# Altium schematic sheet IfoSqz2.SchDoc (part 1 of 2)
size C; Engineer: Daniel Sigg; DocumentNumber: 5; SheetNumber: 17; SheetTotal: 33
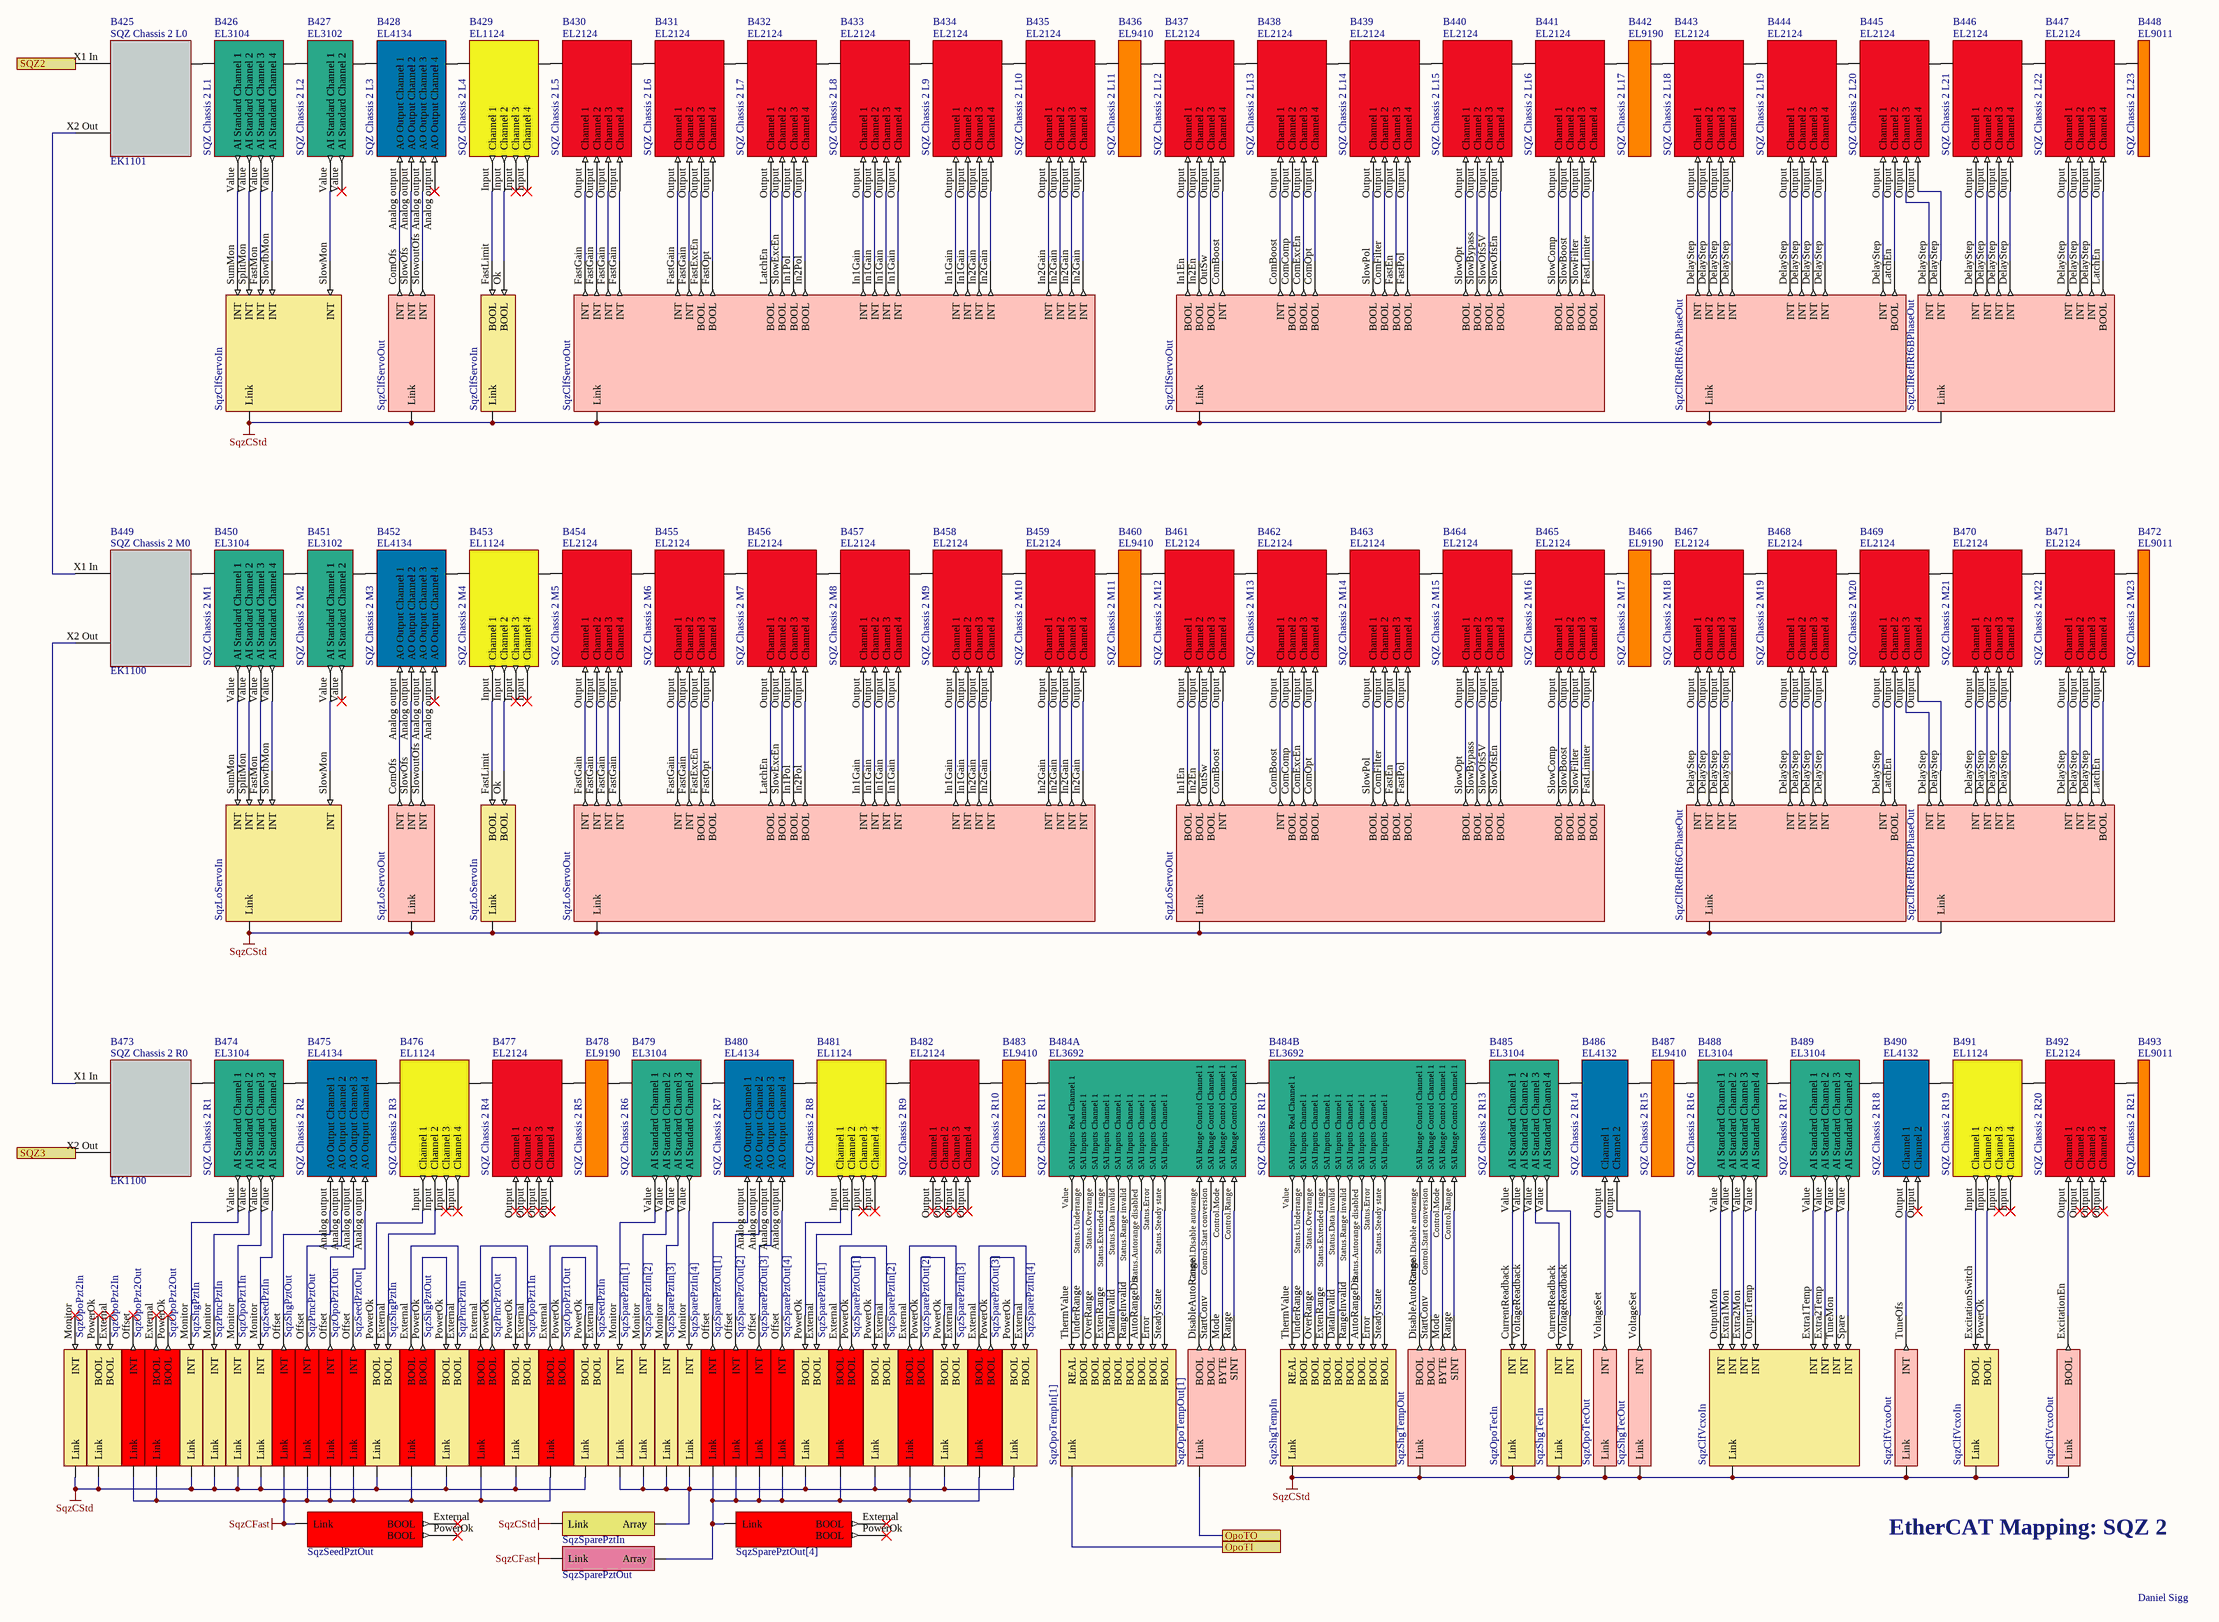
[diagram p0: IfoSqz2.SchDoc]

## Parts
B425  SQZ Chassis 2 L0  Part Number: EK1101
B426  SQZ Chassis 2 L1  Part Number: EL3104  (mechanical)
B427  SQZ Chassis 2 L2  Part Number: EL3102  (mechanical)
B428  SQZ Chassis 2 L3  Part Number: EL4134  (mechanical)
B429  SQZ Chassis 2 L4  Part Number: EL1124  (mechanical)
B430  SQZ Chassis 2 L5  Part Number: EL2124  (mechanical)
B431  SQZ Chassis 2 L6  Part Number: EL2124  (mechanical)
B432  SQZ Chassis 2 L7  Part Number: EL2124  (mechanical)
B433  SQZ Chassis 2 L8  Part Number: EL2124  (mechanical)
B434  SQZ Chassis 2 L9  Part Number: EL2124  (mechanical)
B435  SQZ Chassis 2 L10  Part Number: EL2124  (mechanical)
B436  SQZ Chassis 2 L11  Part Number: EL9410  (mechanical)
B437  SQZ Chassis 2 L12  Part Number: EL2124  (mechanical)
B438  SQZ Chassis 2 L13  Part Number: EL2124  (mechanical)
B439  SQZ Chassis 2 L14  Part Number: EL2124  (mechanical)
B440  SQZ Chassis 2 L15  Part Number: EL2124  (mechanical)
B441  SQZ Chassis 2 L16  Part Number: EL2124  (mechanical)
B442  SQZ Chassis 2 L17  Part Number: EL9190  (mechanical)
B443  SQZ Chassis 2 L18  Part Number: EL2124  (mechanical)
B444  SQZ Chassis 2 L19  Part Number: EL2124  (mechanical)
B445  SQZ Chassis 2 L20  Part Number: EL2124  (mechanical)
B446  SQZ Chassis 2 L21  Part Number: EL2124  (mechanical)
B447  SQZ Chassis 2 L22  Part Number: EL2124  (mechanical)
B448  SQZ Chassis 2 L23  Part Number: EL9011  (mechanical)
B449  SQZ Chassis 2 M0  Part Number: EK1100
B450  SQZ Chassis 2 M1  Part Number: EL3104  (mechanical)
B451  SQZ Chassis 2 M2  Part Number: EL3102  (mechanical)
B452  SQZ Chassis 2 M3  Part Number: EL4134  (mechanical)
B453  SQZ Chassis 2 M4  Part Number: EL1124  (mechanical)
B454  SQZ Chassis 2 M5  Part Number: EL2124  (mechanical)
B455  SQZ Chassis 2 M6  Part Number: EL2124  (mechanical)
B456  SQZ Chassis 2 M7  Part Number: EL2124  (mechanical)
B457  SQZ Chassis 2 M8  Part Number: EL2124  (mechanical)
B458  SQZ Chassis 2 M9  Part Number: EL2124  (mechanical)
B459  SQZ Chassis 2 M10  Part Number: EL2124  (mechanical)
B460  SQZ Chassis 2 M11  Part Number: EL9410  (mechanical)
B461  SQZ Chassis 2 M12  Part Number: EL2124  (mechanical)
B462  SQZ Chassis 2 M13  Part Number: EL2124  (mechanical)
B463  SQZ Chassis 2 M14  Part Number: EL2124  (mechanical)
B464  SQZ Chassis 2 M15  Part Number: EL2124  (mechanical)
B465  SQZ Chassis 2 M16  Part Number: EL2124  (mechanical)
B466  SQZ Chassis 2 M17  Part Number: EL9190  (mechanical)
B467  SQZ Chassis 2 M18  Part Number: EL2124  (mechanical)
B468  SQZ Chassis 2 M19  Part Number: EL2124  (mechanical)
B469  SQZ Chassis 2 M20  Part Number: EL2124  (mechanical)
B470  SQZ Chassis 2 M21  Part Number: EL2124  (mechanical)
B471  SQZ Chassis 2 M22  Part Number: EL2124  (mechanical)
B472  SQZ Chassis 2 M23  Part Number: EL9011  (mechanical)
B473  SQZ Chassis 2 R0  Part Number: EK1100
B474  SQZ Chassis 2 R1  Part Number: EL3104  (mechanical)
B475  SQZ Chassis 2 R2  Part Number: EL4134  (mechanical)
B476  SQZ Chassis 2 R3  Part Number: EL1124  (mechanical)
B477  SQZ Chassis 2 R4  Part Number: EL2124  (mechanical)
B478  SQZ Chassis 2 R5  Part Number: EL9190  (mechanical)
B479  SQZ Chassis 2 R6  Part Number: EL3104  (mechanical)
B480  SQZ Chassis 2 R7  Part Number: EL4134  (mechanical)
B481  SQZ Chassis 2 R8  Part Number: EL1124  (mechanical)
B482  SQZ Chassis 2 R9  Part Number: EL2124  (mechanical)
B483  SQZ Chassis 2 R10  Part Number: EL9410  (mechanical)
B484A  SQZ Chassis 2 R11  Part Number: EL3692  (mechanical)
B484B  SQZ Chassis 2 R12  Part Number: EL3692  (mechanical)
B485  SQZ Chassis 2 R13  Part Number: EL3104  (mechanical)
B486  SQZ Chassis 2 R14  Part Number: EL4132  (mechanical)
B487  SQZ Chassis 2 R15  Part Number: EL9410  (mechanical)
B488  SQZ Chassis 2 R16  Part Number: EL3104  (mechanical)
B489  SQZ Chassis 2 R17  Part Number: EL3104  (mechanical)
B490  SQZ Chassis 2 R18  Part Number: EL4132  (mechanical)
B491  SQZ Chassis 2 R19  Part Number: EL1124  (mechanical)
B492  SQZ Chassis 2 R20  Part Number: EL2124  (mechanical)
B493  SQZ Chassis 2 R21  Part Number: EL9011  (mechanical)
V176  SqzShgTecIn  (no BOM)
V177  SqzShgTecOut  (no BOM)
V289  SqzLoServoIn  (parts A,B of 2)  (no BOM)
V290  SqzLoServoOut  (parts A,B,C of 3)  (no BOM)
V291  SqzClfServoIn  (parts A,B of 2)  (no BOM)
V292  SqzClfServoOut  (parts A,B,C of 3)  (no BOM)
V297  SqzShgTempIn  (no BOM)
V298  SqzShgTempOut  (no BOM)
V303  SqzClfVcxoIn  (parts A,B of 2)  (no BOM)
V304  SqzClfVcxoOut  (parts A,B of 2)  (no BOM)
V305  SqzShgPztIn  (parts A,B of 2)  (no BOM)
V306  SqzPmcPztIn  (parts A,B of 2)  (no BOM)
V307  SqzOpoPzt1In  (parts A,B of 2)  (no BOM)
V308  SqzSeedPztIn  (parts A,B of 2)  (no BOM)
V309  SqzShgPztOut  (parts A,B of 2)  (no BOM)
V310  SqzPmcPztOut  (parts A,B of 2)  (no BOM)
V311  SqzOpoPzt1Out  (parts A,B of 2)  (no BOM)
V312  SqzSeedPztOut  (parts A,B of 2)  (no BOM)
V313  SqzSparePztIn[1]  (parts A,B of 2)  (no BOM)
V314  SqzSparePztIn[2]  (parts A,B of 2)  (no BOM)
V315  SqzSparePztIn[3]  (parts A,B of 2)  (no BOM)
V316  SqzSparePztIn[4]  (parts A,B of 2)  (no BOM)
V317  SqzSparePztOut[1]  (parts A,B of 2)  (no BOM)
V318  SqzSparePztOut[2]  (parts A,B of 2)  (no BOM)
V319  SqzSparePztOut[3]  (parts A,B of 2)  (no BOM)
V320  SqzSparePztOut[4]  (parts A,B of 2)  (no BOM)
V448  SqzClfReflRf6APhaseOut  (no BOM)
V449  SqzClfReflRf6BPhaseOut  (no BOM)
V450  SqzClfReflRf6CPhaseOut  (no BOM)
V452  SqzClfReflRf6DPhaseOut  (no BOM)
V453  SqzOpoTempIn[1]  (no BOM)
V454  SqzOpoTempOut[1]  (no BOM)
V455  SqzOpoTecIn  (no BOM)
V456  SqzOpoTecOut  (no BOM)
V457  SqzSparePztIn  (no BOM)
V458  SqzSparePztOut  (no BOM)
V655  SqzOpoPzt2In  (parts A,B of 2)  (no BOM)
V668  SqzOpoPzt2Out  (parts A,B of 2)  (no BOM)

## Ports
OpoTI, OpoTO, SQZ2, SQZ3

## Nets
SqzCFast: V309.0(Link) V309.1(Link) V310.0(Link) V310.1(Link) V311.0(Link) V311.1(Link) V312.0(Link) V312.1(Link) V458.?1(Link) V668.0(Link) V668.1(Link)
SqzCStd: V176.1(Link) V177.1(Link) V289.0(Link) V289.1(Link) V290.0(Link) V290.1(Link) V290.2(Link) V291.0(Link) V291.1(Link) V292.0(Link) V292.1(Link) V292.2(Link) V297.1(Link) V298.1(Link) V303.0(Link) V303.1(Link) V304.0(Link) V304.1(Link) V305.0(Link) V305.1(Link) V306.0(Link) V306.1(Link) V307.0(Link) V307.1(Link) V308.0(Link) V308.1(Link) V448.?1(Link) V449.?1(Link) V450.?1(Link) V452.?1(Link) V455.1(Link) V456.1(Link) V457.?1(Link) V655.0(Link) V655.1(Link)
OpoTI: V453.1(Link) ; port OpoTI
OpoTO: V454.1(Link) ; port OpoTO
SQZ2: B425.X1_In(A) ; port SQZ2
SQZ3: B473.X2_Out(C) ; port SQZ3
NetB425_Ebus: B425.Ebus(B) B426.Ebus(A)
NetB425_X2 Out: B425.X2_Out(C) B449.X1_In(A)
NetB426_Ebus: B426.Ebus(B) B427.Ebus(A)
NetB426_Value: B426.Value(AI_Standard_Channel_1) V291.SumMon(INT)
NetB426_Value: B426.Value(AI_Standard_Channel_2) V291.SplitMon(INT)  [a separate net that carries the same name]
NetB426_Value: B426.Value(AI_Standard_Channel_3) V291.FastMon(INT)  [a separate net that carries the same name]
NetB426_Value: B426.Value(AI_Standard_Channel_4) V291.SlowfbMon(INT)  [a separate net that carries the same name]
NetB427_Ebus: B427.Ebus(B) B428.Ebus(A)
NetB427_Value: B427.Value(AI_Standard_Channel_1) V291.SlowMon(INT)
NetB428_Analog output: B428.Analog_output(AO_Output_Channel_1) V292.ComOfs(INT)
NetB428_Analog output: B428.Analog_output(AO_Output_Channel_2) V292.SlowOfs(INT)  [a separate net that carries the same name]
NetB428_Analog output: B428.Analog_output(AO_Output_Channel_3) V292.SlowoutOfs(INT)  [a separate net that carries the same name]
NetB428_Ebus: B428.Ebus(B) B429.Ebus(A)
NetB429_Ebus: B429.Ebus(B) B430.Ebus(A)
NetB429_Input: B429.Input(Channel_1) V291.FastLimit(BOOL)
NetB429_Input: B429.Input(Channel_2) V291.Ok(BOOL)  [a separate net that carries the same name]
NetB430_Ebus: B430.Ebus(B) B431.Ebus(A)
NetB430_Output: B430.Output(Channel_1) V292.FastGain(INT)
NetB430_Output: B430.Output(Channel_2) V292.FastGain(INT)  [a separate net that carries the same name]
NetB430_Output: B430.Output(Channel_3) V292.FastGain(INT)  [a separate net that carries the same name]
NetB430_Output: B430.Output(Channel_4) V292.FastGain(INT)  [a separate net that carries the same name]
NetB431_Ebus: B431.Ebus(B) B432.Ebus(A)
NetB431_Output: B431.Output(Channel_1) V292.FastGain(INT)
NetB431_Output: B431.Output(Channel_2) V292.FastGain(INT)  [a separate net that carries the same name]
NetB431_Output: B431.Output(Channel_3) V292.FastExcEn(BOOL)  [a separate net that carries the same name]
NetB431_Output: B431.Output(Channel_4) V292.FastOpt(BOOL)  [a separate net that carries the same name]
NetB432_Ebus: B432.Ebus(B) B433.Ebus(A)
NetB432_Output: B432.Output(Channel_1) V292.LatchEn(BOOL)
NetB432_Output: B432.Output(Channel_2) V292.SlowExcEn(BOOL)  [a separate net that carries the same name]
NetB432_Output: B432.Output(Channel_3) V292.In1Pol(BOOL)  [a separate net that carries the same name]
NetB432_Output: B432.Output(Channel_4) V292.In2Pol(BOOL)  [a separate net that carries the same name]
NetB433_Ebus: B433.Ebus(B) B434.Ebus(A)
NetB433_Output: B433.Output(Channel_1) V292.In1Gain(INT)
NetB433_Output: B433.Output(Channel_2) V292.In1Gain(INT)  [a separate net that carries the same name]
NetB433_Output: B433.Output(Channel_3) V292.In1Gain(INT)  [a separate net that carries the same name]
NetB433_Output: B433.Output(Channel_4) V292.In1Gain(INT)  [a separate net that carries the same name]
NetB434_Ebus: B434.Ebus(B) B435.Ebus(A)
NetB434_Output: B434.Output(Channel_1) V292.In1Gain(INT)
NetB434_Output: B434.Output(Channel_2) V292.In1Gain(INT)  [a separate net that carries the same name]
NetB434_Output: B434.Output(Channel_3) V292.In2Gain(INT)  [a separate net that carries the same name]
NetB434_Output: B434.Output(Channel_4) V292.In2Gain(INT)  [a separate net that carries the same name]
NetB435_Ebus: B435.Ebus(B) B436.Ebus(A)
NetB435_Output: B435.Output(Channel_1) V292.In2Gain(INT)
NetB435_Output: B435.Output(Channel_2) V292.In2Gain(INT)  [a separate net that carries the same name]
NetB435_Output: B435.Output(Channel_3) V292.In2Gain(INT)  [a separate net that carries the same name]
NetB435_Output: B435.Output(Channel_4) V292.In2Gain(INT)  [a separate net that carries the same name]
NetB436_Ebus: B436.Ebus(B) B437.Ebus(A)
NetB437_Ebus: B437.Ebus(B) B438.Ebus(A)
NetB437_Output: B437.Output(Channel_1) V292.In1En(BOOL)
NetB437_Output: B437.Output(Channel_2) V292.In2En(BOOL)  [a separate net that carries the same name]
NetB437_Output: B437.Output(Channel_3) V292.OutSw(BOOL)  [a separate net that carries the same name]
NetB437_Output: B437.Output(Channel_4) V292.ComBoost(INT)  [a separate net that carries the same name]
NetB438_Ebus: B438.Ebus(B) B439.Ebus(A)
NetB438_Output: B438.Output(Channel_1) V292.ComBoost(INT)
NetB438_Output: B438.Output(Channel_2) V292.ComComp(BOOL)  [a separate net that carries the same name]
NetB438_Output: B438.Output(Channel_3) V292.ComExcEn(BOOL)  [a separate net that carries the same name]
NetB438_Output: B438.Output(Channel_4) V292.ComOpt(BOOL)  [a separate net that carries the same name]
NetB439_Ebus: B439.Ebus(B) B440.Ebus(A)
NetB439_Output: B439.Output(Channel_1) V292.SlowPol(BOOL)
NetB439_Output: B439.Output(Channel_2) V292.ComFilter(BOOL)  [a separate net that carries the same name]
NetB439_Output: B439.Output(Channel_3) V292.FastEn(BOOL)  [a separate net that carries the same name]
NetB439_Output: B439.Output(Channel_4) V292.FastPol(BOOL)  [a separate net that carries the same name]
NetB440_Ebus: B440.Ebus(B) B441.Ebus(A)
NetB440_Output: B440.Output(Channel_1) V292.SlowOpt(BOOL)
NetB440_Output: B440.Output(Channel_2) V292.SlowBypass(BOOL)  [a separate net that carries the same name]
NetB440_Output: B440.Output(Channel_3) V292.SlowOfs5V(BOOL)  [a separate net that carries the same name]
NetB440_Output: B440.Output(Channel_4) V292.SlowOfsEn(BOOL)  [a separate net that carries the same name]
NetB441_Ebus: B441.Ebus(B) B442.Ebus(A)
NetB441_Output: B441.Output(Channel_1) V292.SlowComp(BOOL)
NetB441_Output: B441.Output(Channel_2) V292.SlowBoost(BOOL)  [a separate net that carries the same name]
NetB441_Output: B441.Output(Channel_3) V292.SlowFilter(BOOL)  [a separate net that carries the same name]
NetB441_Output: B441.Output(Channel_4) V292.FastLimiter(BOOL)  [a separate net that carries the same name]
NetB442_Ebus: B442.Ebus(B) B443.Ebus(A)
NetB443_Ebus: B443.Ebus(B) B444.Ebus(A)
NetB443_Output: B443.Output(Channel_1) V448.DelayStep(INT)
NetB443_Output: B443.Output(Channel_2) V448.DelayStep(INT)  [a separate net that carries the same name]
NetB443_Output: B443.Output(Channel_3) V448.DelayStep(INT)  [a separate net that carries the same name]
NetB443_Output: B443.Output(Channel_4) V448.DelayStep(INT)  [a separate net that carries the same name]
NetB444_Ebus: B444.Ebus(B) B445.Ebus(A)
NetB444_Output: B444.Output(Channel_1) V448.DelayStep(INT)
NetB444_Output: B444.Output(Channel_2) V448.DelayStep(INT)  [a separate net that carries the same name]
NetB444_Output: B444.Output(Channel_3) V448.DelayStep(INT)  [a separate net that carries the same name]
NetB444_Output: B444.Output(Channel_4) V448.DelayStep(INT)  [a separate net that carries the same name]
NetB445_Ebus: B445.Ebus(B) B446.Ebus(A)
NetB445_Output: B445.Output(Channel_1) V448.DelayStep(INT)
NetB445_Output: B445.Output(Channel_2) V448.LatchEn(BOOL)  [a separate net that carries the same name]
NetB445_Output: B445.Output(Channel_3) V449.DelayStep(INT)  [a separate net that carries the same name]
NetB445_Output: B445.Output(Channel_4) V449.DelayStep(INT)  [a separate net that carries the same name]
NetB446_Ebus: B446.Ebus(B) B447.Ebus(A)
NetB446_Output: B446.Output(Channel_1) V449.DelayStep(INT)
NetB446_Output: B446.Output(Channel_2) V449.DelayStep(INT)  [a separate net that carries the same name]
NetB446_Output: B446.Output(Channel_3) V449.DelayStep(INT)  [a separate net that carries the same name]
NetB446_Output: B446.Output(Channel_4) V449.DelayStep(INT)  [a separate net that carries the same name]
NetB447_Ebus: B447.Ebus(B) B448.Ebus(A)
NetB447_Output: B447.Output(Channel_1) V449.DelayStep(INT)
NetB447_Output: B447.Output(Channel_2) V449.DelayStep(INT)  [a separate net that carries the same name]
NetB447_Output: B447.Output(Channel_3) V449.DelayStep(INT)  [a separate net that carries the same name]
NetB447_Output: B447.Output(Channel_4) V449.LatchEn(BOOL)  [a separate net that carries the same name]
NetB449_Ebus: B449.Ebus(B) B450.Ebus(A)
NetB449_X2 Out: B449.X2_Out(C) B473.X1_In(A)
NetB450_Ebus: B450.Ebus(B) B451.Ebus(A)
NetB450_Value: B450.Value(AI_Standard_Channel_1) V289.SumMon(INT)
NetB450_Value: B450.Value(AI_Standard_Channel_2) V289.SplitMon(INT)  [a separate net that carries the same name]
NetB450_Value: B450.Value(AI_Standard_Channel_3) V289.FastMon(INT)  [a separate net that carries the same name]
NetB450_Value: B450.Value(AI_Standard_Channel_4) V289.SlowfbMon(INT)  [a separate net that carries the same name]
NetB451_Ebus: B451.Ebus(B) B452.Ebus(A)
NetB451_Value: B451.Value(AI_Standard_Channel_1) V289.SlowMon(INT)
NetB452_Analog output: B452.Analog_output(AO_Output_Channel_1) V290.ComOfs(INT)
NetB452_Analog output: B452.Analog_output(AO_Output_Channel_2) V290.SlowOfs(INT)  [a separate net that carries the same name]
NetB452_Analog output: B452.Analog_output(AO_Output_Channel_3) V290.SlowoutOfs(INT)  [a separate net that carries the same name]
NetB452_Ebus: B452.Ebus(B) B453.Ebus(A)
NetB453_Ebus: B453.Ebus(B) B454.Ebus(A)
NetB453_Input: B453.Input(Channel_1) V289.FastLimit(BOOL)
NetB453_Input: B453.Input(Channel_2) V289.Ok(BOOL)  [a separate net that carries the same name]
NetB454_Ebus: B454.Ebus(B) B455.Ebus(A)
NetB454_Output: B454.Output(Channel_1) V290.FastGain(INT)
NetB454_Output: B454.Output(Channel_2) V290.FastGain(INT)  [a separate net that carries the same name]
NetB454_Output: B454.Output(Channel_3) V290.FastGain(INT)  [a separate net that carries the same name]
NetB454_Output: B454.Output(Channel_4) V290.FastGain(INT)  [a separate net that carries the same name]
NetB455_Ebus: B455.Ebus(B) B456.Ebus(A)
NetB455_Output: B455.Output(Channel_1) V290.FastGain(INT)
NetB455_Output: B455.Output(Channel_2) V290.FastGain(INT)  [a separate net that carries the same name]
NetB455_Output: B455.Output(Channel_3) V290.FastExcEn(BOOL)  [a separate net that carries the same name]
NetB455_Output: B455.Output(Channel_4) V290.FastOpt(BOOL)  [a separate net that carries the same name]
NetB456_Ebus: B456.Ebus(B) B457.Ebus(A)
NetB456_Output: B456.Output(Channel_1) V290.LatchEn(BOOL)
NetB456_Output: B456.Output(Channel_2) V290.SlowExcEn(BOOL)  [a separate net that carries the same name]
NetB456_Output: B456.Output(Channel_3) V290.In1Pol(BOOL)  [a separate net that carries the same name]
NetB456_Output: B456.Output(Channel_4) V290.In2Pol(BOOL)  [a separate net that carries the same name]
NetB457_Ebus: B457.Ebus(B) B458.Ebus(A)
NetB457_Output: B457.Output(Channel_1) V290.In1Gain(INT)
NetB457_Output: B457.Output(Channel_2) V290.In1Gain(INT)  [a separate net that carries the same name]
NetB457_Output: B457.Output(Channel_3) V290.In1Gain(INT)  [a separate net that carries the same name]
NetB457_Output: B457.Output(Channel_4) V290.In1Gain(INT)  [a separate net that carries the same name]
NetB458_Ebus: B458.Ebus(B) B459.Ebus(A)
NetB458_Output: B458.Output(Channel_1) V290.In1Gain(INT)
NetB458_Output: B458.Output(Channel_2) V290.In1Gain(INT)  [a separate net that carries the same name]
NetB458_Output: B458.Output(Channel_3) V290.In2Gain(INT)  [a separate net that carries the same name]
NetB458_Output: B458.Output(Channel_4) V290.In2Gain(INT)  [a separate net that carries the same name]
NetB459_Ebus: B459.Ebus(B) B460.Ebus(A)
NetB459_Output: B459.Output(Channel_1) V290.In2Gain(INT)
NetB459_Output: B459.Output(Channel_2) V290.In2Gain(INT)  [a separate net that carries the same name]
NetB459_Output: B459.Output(Channel_3) V290.In2Gain(INT)  [a separate net that carries the same name]
NetB459_Output: B459.Output(Channel_4) V290.In2Gain(INT)  [a separate net that carries the same name]
NetB460_Ebus: B460.Ebus(B) B461.Ebus(A)
NetB461_Ebus: B461.Ebus(B) B462.Ebus(A)
NetB461_Output: B461.Output(Channel_1) V290.In1En(BOOL)
NetB461_Output: B461.Output(Channel_2) V290.In2En(BOOL)  [a separate net that carries the same name]
NetB461_Output: B461.Output(Channel_3) V290.OutSw(BOOL)  [a separate net that carries the same name]
NetB461_Output: B461.Output(Channel_4) V290.ComBoost(INT)  [a separate net that carries the same name]
NetB462_Ebus: B462.Ebus(B) B463.Ebus(A)
NetB462_Output: B462.Output(Channel_1) V290.ComBoost(INT)
NetB462_Output: B462.Output(Channel_2) V290.ComComp(BOOL)  [a separate net that carries the same name]
NetB462_Output: B462.Output(Channel_3) V290.ComExcEn(BOOL)  [a separate net that carries the same name]
NetB462_Output: B462.Output(Channel_4) V290.ComOpt(BOOL)  [a separate net that carries the same name]
NetB463_Ebus: B463.Ebus(B) B464.Ebus(A)
NetB463_Output: B463.Output(Channel_1) V290.SlowPol(BOOL)
NetB463_Output: B463.Output(Channel_2) V290.ComFilter(BOOL)  [a separate net that carries the same name]
NetB463_Output: B463.Output(Channel_3) V290.FastEn(BOOL)  [a separate net that carries the same name]
NetB463_Output: B463.Output(Channel_4) V290.FastPol(BOOL)  [a separate net that carries the same name]
NetB464_Ebus: B464.Ebus(B) B465.Ebus(A)
NetB464_Output: B464.Output(Channel_1) V290.SlowOpt(BOOL)
NetB464_Output: B464.Output(Channel_2) V290.SlowBypass(BOOL)  [a separate net that carries the same name]
NetB464_Output: B464.Output(Channel_3) V290.SlowOfs5V(BOOL)  [a separate net that carries the same name]
NetB464_Output: B464.Output(Channel_4) V290.SlowOfsEn(BOOL)  [a separate net that carries the same name]
NetB465_Ebus: B465.Ebus(B) B466.Ebus(A)
NetB465_Output: B465.Output(Channel_1) V290.SlowComp(BOOL)
NetB465_Output: B465.Output(Channel_2) V290.SlowBoost(BOOL)  [a separate net that carries the same name]
NetB465_Output: B465.Output(Channel_3) V290.SlowFilter(BOOL)  [a separate net that carries the same name]
NetB465_Output: B465.Output(Channel_4) V290.FastLimiter(BOOL)  [a separate net that carries the same name]
NetB466_Ebus: B466.Ebus(B) B467.Ebus(A)
NetB467_Ebus: B467.Ebus(B) B468.Ebus(A)
NetB467_Output: B467.Output(Channel_1) V450.DelayStep(INT)
NetB467_Output: B467.Output(Channel_2) V450.DelayStep(INT)  [a separate net that carries the same name]
NetB467_Output: B467.Output(Channel_3) V450.DelayStep(INT)  [a separate net that carries the same name]
NetB467_Output: B467.Output(Channel_4) V450.DelayStep(INT)  [a separate net that carries the same name]
NetB468_Ebus: B468.Ebus(B) B469.Ebus(A)
NetB468_Output: B468.Output(Channel_1) V450.DelayStep(INT)
NetB468_Output: B468.Output(Channel_2) V450.DelayStep(INT)  [a separate net that carries the same name]
NetB468_Output: B468.Output(Channel_3) V450.DelayStep(INT)  [a separate net that carries the same name]
NetB468_Output: B468.Output(Channel_4) V450.DelayStep(INT)  [a separate net that carries the same name]
NetB469_Ebus: B469.Ebus(B) B470.Ebus(A)
NetB469_Output: B469.Output(Channel_1) V450.DelayStep(INT)
NetB469_Output: B469.Output(Channel_2) V450.LatchEn(BOOL)  [a separate net that carries the same name]
NetB469_Output: B469.Output(Channel_3) V452.DelayStep(INT)  [a separate net that carries the same name]
NetB469_Output: B469.Output(Channel_4) V452.DelayStep(INT)  [a separate net that carries the same name]
NetB470_Ebus: B470.Ebus(B) B471.Ebus(A)
NetB470_Output: B470.Output(Channel_1) V452.DelayStep(INT)
NetB470_Output: B470.Output(Channel_2) V452.DelayStep(INT)  [a separate net that carries the same name]
NetB470_Output: B470.Output(Channel_3) V452.DelayStep(INT)  [a separate net that carries the same name]
NetB470_Output: B470.Output(Channel_4) V452.DelayStep(INT)  [a separate net that carries the same name]
NetB471_Ebus: B471.Ebus(B) B472.Ebus(A)
NetB471_Output: B471.Output(Channel_1) V452.DelayStep(INT)
NetB471_Output: B471.Output(Channel_2) V452.DelayStep(INT)  [a separate net that carries the same name]
NetB471_Output: B471.Output(Channel_3) V452.DelayStep(INT)  [a separate net that carries the same name]
NetB471_Output: B471.Output(Channel_4) V452.LatchEn(BOOL)  [a separate net that carries the same name]
NetB473_Ebus: B473.Ebus(B) B474.Ebus(A)
NetB474_Ebus: B474.Ebus(B) B475.Ebus(A)
NetB474_Value: B474.Value(AI_Standard_Channel_1) V305.Monitor(INT)
NetB474_Value: B474.Value(AI_Standard_Channel_2) V306.Monitor(INT)  [a separate net that carries the same name]
NetB474_Value: B474.Value(AI_Standard_Channel_3) V307.Monitor(INT)  [a separate net that carries the same name]
NetB474_Value: B474.Value(AI_Standard_Channel_4) V308.Monitor(INT)  [a separate net that carries the same name]
NetB475_Analog output: B475.Analog_output(AO_Output_Channel_1) V309.Offset(INT)
NetB475_Analog output: B475.Analog_output(AO_Output_Channel_2) V310.Offset(INT)  [a separate net that carries the same name]
NetB475_Analog output: B475.Analog_output(AO_Output_Channel_3) V311.Offset(INT)  [a separate net that carries the same name]
NetB475_Analog output: B475.Analog_output(AO_Output_Channel_4) V312.Offset(INT)  [a separate net that carries the same name]
NetB475_Ebus: B475.Ebus(B) B476.Ebus(A)
NetB476_Ebus: B476.Ebus(B) B477.Ebus(A)
NetB476_Input: B476.Input(Channel_1) V305.PowerOk(BOOL)
NetB476_Input: B476.Input(Channel_2) V305.External(BOOL)  [a separate net that carries the same name]
NetB477_Ebus: B477.Ebus(B) B478.Ebus(A)
NetB478_Ebus: B478.Ebus(B) B479.Ebus(A)
NetB479_Ebus: B479.Ebus(B) B480.Ebus(A)
NetB479_Value: B479.Value(AI_Standard_Channel_1) V313.Monitor(INT)
NetB479_Value: B479.Value(AI_Standard_Channel_2) V314.Monitor(INT)  [a separate net that carries the same name]
NetB479_Value: B479.Value(AI_Standard_Channel_3) V315.Monitor(INT)  [a separate net that carries the same name]
NetB479_Value: B479.Value(AI_Standard_Channel_4) V316.Monitor(INT)  [a separate net that carries the same name]
NetB480_Analog output: B480.Analog_output(AO_Output_Channel_1) V317.Offset(INT)
NetB480_Analog output: B480.Analog_output(AO_Output_Channel_2) V318.Offset(INT)  [a separate net that carries the same name]
NetB480_Analog output: B480.Analog_output(AO_Output_Channel_3) V319.Offset(INT)  [a separate net that carries the same name]
NetB480_Analog output: B480.Analog_output(AO_Output_Channel_4) V320.Offset(INT)  [a separate net that carries the same name]
NetB480_Ebus: B480.Ebus(B) B481.Ebus(A)
NetB481_Ebus: B481.Ebus(B) B482.Ebus(A)
NetB481_Input: B481.Input(Channel_1) V313.PowerOk(BOOL)
NetB481_Input: B481.Input(Channel_2) V313.External(BOOL)  [a separate net that carries the same name]
NetB482_Ebus: B482.Ebus(B) B483.Ebus(A)
NetB483_Ebus: B483.Ebus(B) B484A.Ebus(A)
NetB484A_Control.Disable autorange: B484A.Control.Disable_autorange(SAI_Range_Control_Channel_1) V454.DisableAutoRange(BOOL)
NetB484A_Control.Mode: B484A.Control.Mode(SAI_Range_Control_Channel_1) V454.Mode(BYTE)
NetB484A_Control.Range: B484A.Control.Range(SAI_Range_Control_Channel_1) V454.Range(SINT)
NetB484A_Control.Start conversion: B484A.Control.Start_conversion(SAI_Range_Control_Channel_1) V454.StartConv(BOOL)
NetB484A_Ebus: B484A.Ebus(B) B484B.Ebus(A)
NetB484A_Status.Autorange disabled: B484A.Status.Autorange_disabled(SAI_Inputs_Channel_1) V453.AutoRangeDis(BOOL)
NetB484A_Status.Data invalid: B484A.Status.Data_invalid(SAI_Inputs_Channel_1) V453.DataInvalid(BOOL)
NetB484A_Status.Error: B484A.Status.Error(SAI_Inputs_Channel_1) V453.Error(BOOL)
NetB484A_Status.Extended range: B484A.Status.Extended_range(SAI_Inputs_Channel_1) V453.ExtenRange(BOOL)
NetB484A_Status.Overrange: B484A.Status.Overrange(SAI_Inputs_Channel_1) V453.OverRange(BOOL)
NetB484A_Status.Range invalid: B484A.Status.Range_invalid(SAI_Inputs_Channel_1) V453.RangeInvalid(BOOL)
NetB484A_Status.Steady state: B484A.Status.Steady_state(SAI_Inputs_Channel_1) V453.SteadyState(BOOL)
NetB484A_Status.Underrange: B484A.Status.Underrange(SAI_Inputs_Channel_1) V453.UnderRange(BOOL)
NetB484A_Value: B484A.Value(SAI_Inputs_Real_Channel_1) V453.ThermValue(REAL)
NetB484B_Control.Disable autorange: B484B.Control.Disable_autorange(SAI_Range_Control_Channel_1) V298.DisableAutoRange(BOOL)
NetB484B_Control.Mode: B484B.Control.Mode(SAI_Range_Control_Channel_1) V298.Mode(BYTE)
NetB484B_Control.Range: B484B.Control.Range(SAI_Range_Control_Channel_1) V298.Range(SINT)
NetB484B_Control.Start conversion: B484B.Control.Start_conversion(SAI_Range_Control_Channel_1) V298.StartConv(BOOL)
NetB484B_Ebus: B484B.Ebus(B) B485.Ebus(A)
NetB484B_Status.Autorange disabled: B484B.Status.Autorange_disabled(SAI_Inputs_Channel_1) V297.AutoRangeDis(BOOL)
NetB484B_Status.Data invalid: B484B.Status.Data_invalid(SAI_Inputs_Channel_1) V297.DataInvalid(BOOL)
NetB484B_Status.Error: B484B.Status.Error(SAI_Inputs_Channel_1) V297.Error(BOOL)
NetB484B_Status.Extended range: B484B.Status.Extended_range(SAI_Inputs_Channel_1) V297.ExtenRange(BOOL)
NetB484B_Status.Overrange: B484B.Status.Overrange(SAI_Inputs_Channel_1) V297.OverRange(BOOL)
NetB484B_Status.Range invalid: B484B.Status.Range_invalid(SAI_Inputs_Channel_1) V297.RangeInvalid(BOOL)
NetB484B_Status.Steady state: B484B.Status.Steady_state(SAI_Inputs_Channel_1) V297.SteadyState(BOOL)
NetB484B_Status.Underrange: B484B.Status.Underrange(SAI_Inputs_Channel_1) V297.UnderRange(BOOL)
NetB484B_Value: B484B.Value(SAI_Inputs_Real_Channel_1) V297.ThermValue(REAL)
NetB485_Ebus: B485.Ebus(B) B486.Ebus(A)
NetB485_Value: B485.Value(AI_Standard_Channel_1) V455.CurrentReadback(INT)
NetB485_Value: B485.Value(AI_Standard_Channel_2) V455.VoltageReadback(INT)  [a separate net that carries the same name]
NetB485_Value: B485.Value(AI_Standard_Channel_3) V176.CurrentReadback(INT)  [a separate net that carries the same name]
NetB485_Value: B485.Value(AI_Standard_Channel_4) V176.VoltageReadback(INT)  [a separate net that carries the same name]
NetB486_Ebus: B486.Ebus(B) B487.Ebus(A)
NetB486_Output: B486.Output(Channel_1) V456.VoltageSet(INT)
NetB486_Output: B486.Output(Channel_2) V177.VoltageSet(INT)  [a separate net that carries the same name]
NetB487_Ebus: B487.Ebus(B) B488.Ebus(A)
NetB488_Ebus: B488.Ebus(B) B489.Ebus(A)
NetB488_Value: B488.Value(AI_Standard_Channel_1) V303.OutputMon(INT)
NetB488_Value: B488.Value(AI_Standard_Channel_2) V303.Extra1Mon(INT)  [a separate net that carries the same name]
NetB488_Value: B488.Value(AI_Standard_Channel_3) V303.Extra2Mon(INT)  [a separate net that carries the same name]
NetB488_Value: B488.Value(AI_Standard_Channel_4) V303.OutputTemp(INT)  [a separate net that carries the same name]
NetB489_Ebus: B489.Ebus(B) B490.Ebus(A)
NetB489_Value: B489.Value(AI_Standard_Channel_1) V303.Extra1Temp(INT)
NetB489_Value: B489.Value(AI_Standard_Channel_2) V303.Extra2Temp(INT)  [a separate net that carries the same name]
NetB489_Value: B489.Value(AI_Standard_Channel_3) V303.TuneMon(INT)  [a separate net that carries the same name]
NetB489_Value: B489.Value(AI_Standard_Channel_4) V303.Spare(INT)  [a separate net that carries the same name]
NetB490_Ebus: B490.Ebus(B) B491.Ebus(A)
NetB490_Output: B490.Output(Channel_1) V304.TuneOfs(INT)
NetB491_Ebus: B491.Ebus(B) B492.Ebus(A)
NetB491_Input: B491.Input(Channel_1) V303.ExcitationSwitch(BOOL)
NetB491_Input: B491.Input(Channel_2) V303.PowerOk(BOOL)  [a separate net that carries the same name]
NetB492_Ebus: B492.Ebus(B) B493.Ebus(A)
NetB492_Output: B492.Output(Channel_1) V304.ExcitationEn(BOOL)
NetV306_External: V306.External(BOOL) V309.External(BOOL)
NetV306_PowerOk: V306.PowerOk(BOOL) V309.PowerOk(BOOL)
NetV307_External: V307.External(BOOL) V310.External(BOOL)
NetV307_PowerOk: V307.PowerOk(BOOL) V310.PowerOk(BOOL)
NetV308_External: V308.External(BOOL) V311.External(BOOL)
NetV308_PowerOk: V308.PowerOk(BOOL) V311.PowerOk(BOOL)
NetV313_0: V313.0(Link) V313.1(Link) V314.0(Link) V314.1(Link) V315.0(Link) V315.1(Link) V316.0(Link) V316.1(Link) V457.?2(Array)
NetV314_External: V314.External(BOOL) V317.External(BOOL)
NetV314_PowerOk: V314.PowerOk(BOOL) V317.PowerOk(BOOL)
NetV315_External: V315.External(BOOL) V318.External(BOOL)
NetV315_PowerOk: V315.PowerOk(BOOL) V318.PowerOk(BOOL)
NetV316_External: V316.External(BOOL) V319.External(BOOL)
NetV316_PowerOk: V316.PowerOk(BOOL) V319.PowerOk(BOOL)
NetV317_0: V317.0(Link) V317.1(Link) V318.0(Link) V318.1(Link) V319.0(Link) V319.1(Link) V320.0(Link) V320.1(Link) V458.?2(Array)

Not connected (* = marked no-connect by the designer): B477 Output(Channel_1)*; B482 Output(Channel_1)*; V312 External(BOOL)* PowerOk(BOOL)*; V320 External(BOOL)* PowerOk(BOOL)*; V655 External(BOOL)* Monitor(INT)* PowerOk(BOOL)*; V668 External(BOOL)* Offset(INT)* PowerOk(BOOL)*

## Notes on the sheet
- EtherCAT Mapping: SQZ 2
- Daniel Sigg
